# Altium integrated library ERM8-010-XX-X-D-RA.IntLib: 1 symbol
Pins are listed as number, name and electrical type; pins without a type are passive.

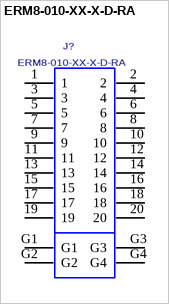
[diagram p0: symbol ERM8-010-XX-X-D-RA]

## ERM8-010-XX-X-D-RA
designator J?
0.8MM DUAL ROW RIGHT ANGLE ASSEMBLY, 20 PINS.; MANUFACTURER: SAMTEC
footprint ERM8-010-XX-X-D-RA
pins: 1, 2, 3, 4, 5, 6, 7, 8, 9, 10, 11, 12, 13, 14, 15, 16, 17, 18, 19, 20, G1, G2, G3, G4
